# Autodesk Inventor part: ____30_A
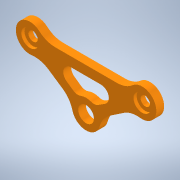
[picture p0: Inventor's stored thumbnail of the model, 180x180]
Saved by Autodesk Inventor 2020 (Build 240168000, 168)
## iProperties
Created: 2017-09
Part Number: ____30_A
Material: Générique
Document SubType Name: Modeling
Designer: bruno
Density: 1 g/cm^3
Appearance: Orange
Mass: 6.65449 g
Surface Area: 46.4625 cm^2
Volume: 6.65449 cm^3
Sending System: SolidWorks 2016
Author: bruno
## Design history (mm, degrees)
feature "Importée1"
node "Solide1"
